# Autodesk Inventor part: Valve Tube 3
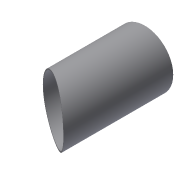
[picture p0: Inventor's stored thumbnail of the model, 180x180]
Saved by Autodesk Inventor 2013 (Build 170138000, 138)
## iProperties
Created: 2012-08
Part Number: Valve Tube 3
Document SubType Name: Modeling
Designer: dms52
Density: 1 g/cm^3
Material: Generic
Author: dms52
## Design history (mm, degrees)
sketch "Sketch1"
  geometry: C1 r 38.1 at (0, 0); C2 r 36.449 at (0, 0); 1 further point
  constraints: 2 centre point, 2 coincident
  dimensions: "d0" = 1.651 radial gap between concentric circles of C2 C1; "d1" = 76.2 diameter of C1
extrude "Extrusion1" new body sketch "Sketch1" distance "d2" = 177.8; taper "d3" = 0 deg
sketch "Sketch3"
  geometry: L1 (0, -349.253)-(0, 1855.132) reference; L2 (-38.1, 0)-(38.1, 0) reference; C1 r 476.25 at (254, 523.24); 1 further point
  constraints: 1 centre point
  dimensions: "d6" = 952.5 diameter of C1; "d7" = 254 distance from line of L1 C1.centre; "d8" = 523.24 distance from line of L2 C1.centre
extrude "Extrusion3" cut sketch "Sketch3" stored distance "d9" = 0; taper "d10" = 0 deg
body "Solid1"
